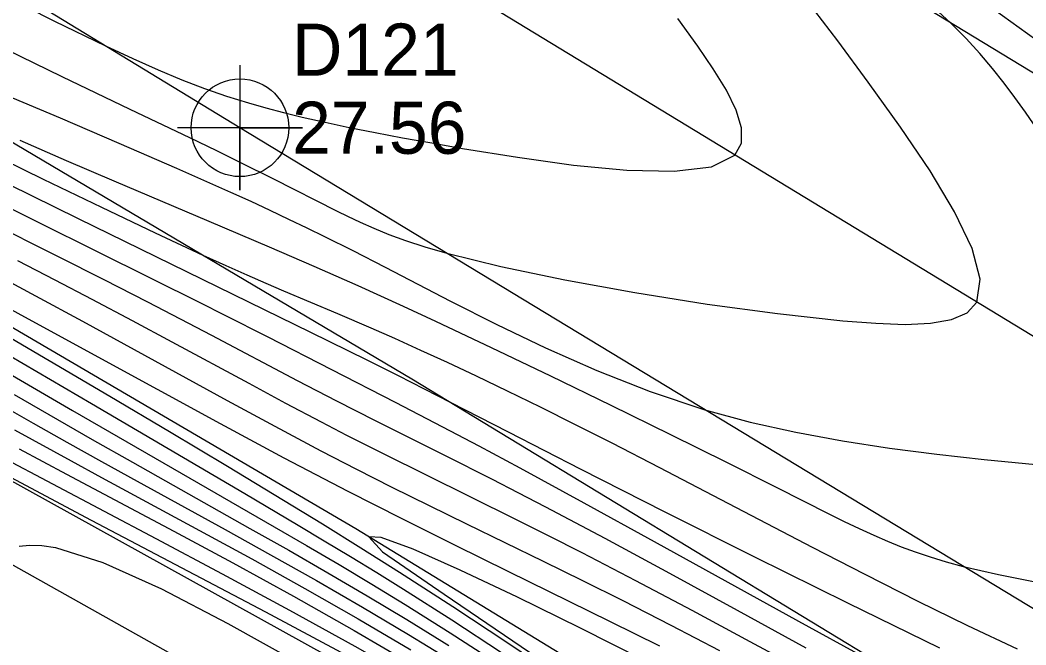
# Model space of a CAD drawing. Extents: x 2356077 to 2359823, y 225951 to 227822.
# Drawn here: x 2356454.61 to 2356502.87, y 227359.99 to 227389.97 of the extents above; entities that cross this region are included whole.
import ezdxf

# ---------------------------------------------------------------- set-up
doc = ezdxf.new("R2010")
doc.units = 0
for name, color, linetype in [('DTM Contours Major', 7, 'Continuous'), ('DTM Contours Minor', 7, 'Continuous'), ('Exist DTM Breakline', 7, 'Continuous'), ('Exist DTM Crownline', 7, 'Continuous'), ('Exist Roads EOP', 7, 'Continuous'), ('Exist Roads EOP Cogo Elevation', 7, 'Continuous'), ('Exist Roads EOP Cogo Number', 7, 'Continuous'), ('Exist Roads EOP Cogo Point CELL', 7, 'Continuous'), ('PH Exist DTM Breakline', 7, 'Continuous')]:
    doc.layers.add(name, color=color, linetype=linetype)

msp = doc.modelspace()

# ---------------------------------------------------------------- linework, layer by layer
at = {"layer": 'DTM Contours Major'}
for points in [[(2356503.336, 227389.017), (2356501.338, 227390.466), (2356499.11, 227392.097), (2356494.152, 227395.755), (2356488.824, 227399.691), (2356478.635, 227407.192), (2356476.063, 227409.092), (2356473.475, 227411.013), (2356472.171, 227411.984), (2356462.737, 227419.043), (2356459.663, 227421.332), (2356456.7, 227423.52), (2356453.891, 227425.566)], [(2356454.591, 227384.202), (2356456.817, 227383.239), (2356459.111, 227382.259), (2356463.673, 227380.327), (2356466.567, 227379.093), (2356468.708, 227378.164), (2356470.809, 227377.231), (2356472.991, 227376.238), (2356474.536, 227375.522), (2356477.209, 227374.261), (2356480.054, 227372.898), (2356482.96, 227371.488), (2356485.814, 227370.088), (2356488.505, 227368.753), (2356490.922, 227367.539), (2356493.408, 227366.282), (2356494.153, 227365.915), (2356494.87, 227365.571), (2356495.57, 227365.25), (2356496.221, 227364.967), (2356496.879, 227364.7), (2356497.558, 227364.447), (2356498.272, 227364.206), (2356499.036, 227363.975), (2356499.865, 227363.751), (2356501.56, 227363.358), (2356503.473, 227362.982)], [(2356492.468, 227358.61), (2356489.639, 227360.142), (2356486.851, 227361.639), (2356484.151, 227363.069), (2356481.582, 227364.403), (2356479.957, 227365.229), (2356478.402, 227366.007), (2356474.073, 227368.142), (2356472.106, 227369.12), (2356470.295, 227370.041), (2356469.068, 227370.678), (2356467.363, 227371.579), (2356465.596, 227372.527), (2356461.908, 227374.518), (2356460.004, 227375.54), (2356458.071, 227376.566), (2356456.293, 227377.495), (2356454.498, 227378.421)], [(2356448.17, 227376.445), (2356457.12, 227371.24), (2356461.502, 227368.703), (2356466.804, 227365.654), (2356468.36, 227364.753), (2356469.919, 227363.838), (2356471.491, 227362.898), (2356473.086, 227361.925), (2356475.245, 227360.57), (2356477.454, 227359.143)], [(2356485.329, 227350.492), (2356479.719, 227354.504), (2356478.749, 227355.126), (2356477.772, 227355.742), (2356476.779, 227356.357), (2356475.758, 227356.977), (2356474.698, 227357.608), (2356473.588, 227358.257), (2356470.681, 227359.908), (2356467.549, 227361.635), (2356464.322, 227363.38), (2356461.133, 227365.083), (2356453.705, 227369.014)]]:
    msp.add_lwpolyline(points, dxfattribs=at)
at = {"layer": 'DTM Contours Minor'}
for points in [[(2356453.561, 227391.29), (2356456.269, 227389.926), (2356458.703, 227388.738), (2356460.022, 227388.123), (2356461.237, 227387.584), (2356462.374, 227387.111), (2356463.458, 227386.694), (2356464.516, 227386.325), (2356465.573, 227385.994), (2356466.401, 227385.758), (2356467.256, 227385.534), (2356468.152, 227385.316), (2356469.242, 227385.069), (2356470.405, 227384.823), (2356471.644, 227384.576), (2356472.961, 227384.326), (2356474.359, 227384.074), (2356475.841, 227383.817), (2356478.47, 227383.387), (2356481.159, 227383.013), (2356483.727, 227382.766), (2356485.995, 227382.716), (2356487.782, 227382.934), (2356488.91, 227383.493), (2356489.222, 227384.07), (2356489.223, 227384.798), (2356488.965, 227385.653), (2356488.497, 227386.608), (2356487.869, 227387.639), (2356487.132, 227388.721), (2356486.173, 227390.043)], [(2356503.414, 227384.742), (2356502.847, 227385.553), (2356502.343, 227386.252), (2356501.82, 227386.949), (2356501.263, 227387.65), (2356500.659, 227388.362), (2356499.993, 227389.091), (2356499.253, 227389.845), (2356497.546, 227391.42)], [(2356451.94, 227389.541), (2356456.617, 227387.266), (2356459.871, 227385.704), (2356462.747, 227384.33), (2356464.036, 227383.709), (2356465.223, 227383.129), (2356466.732, 227382.376), (2356469.83, 227380.8), (2356470.315, 227380.56), (2356470.928, 227380.269), (2356471.583, 227379.978), (2356472.302, 227379.686), (2356473.11, 227379.391), (2356474.028, 227379.092), (2356475.079, 227378.788), (2356477.677, 227378.147), (2356480.747, 227377.506), (2356484.104, 227376.895), (2356487.569, 227376.344), (2356490.957, 227375.883), (2356494.089, 227375.543), (2356495.667, 227375.42), (2356497.078, 227375.37), (2356498.297, 227375.421), (2356499.293, 227375.597), (2356500.042, 227375.926), (2356500.513, 227376.433), (2356500.679, 227377.537), (2356500.289, 227379.009), (2356499.449, 227380.769), (2356498.268, 227382.739), (2356496.852, 227384.838), (2356495.307, 227386.989), (2356493.838, 227388.971), (2356492.372, 227390.896)], [(2356453.748, 227386.447), (2356456.527, 227385.273), (2356459.356, 227384.066), (2356462.122, 227382.866), (2356464.712, 227381.714), (2356465.675, 227381.275), (2356466.6, 227380.846), (2356467.494, 227380.425), (2356468.365, 227380.007), (2356469.22, 227379.589), (2356470.577, 227378.911), (2356472.125, 227378.118), (2356475.263, 227376.488), (2356477.478, 227375.364), (2356479.822, 227374.237), (2356482.28, 227373.15), (2356484.835, 227372.146), (2356487.471, 227371.27), (2356489.635, 227370.682), (2356491.835, 227370.19), (2356494.065, 227369.78), (2356496.318, 227369.436), (2356498.589, 227369.144), (2356500.871, 227368.89), (2356503.343, 227368.651)], [(2356502.461, 227359.79), (2356500.079, 227360.905), (2356497.699, 227362.075), (2356495.161, 227363.358), (2356492.631, 227364.661), (2356485.306, 227368.484), (2356483.021, 227369.662), (2356481.262, 227370.553), (2356479.584, 227371.388), (2356477.995, 227372.165), (2356476.503, 227372.881), (2356475.116, 227373.535), (2356473.84, 227374.123), (2356472.591, 227374.686), (2356471.447, 227375.189), (2356469.85, 227375.872), (2356467.261, 227376.964), (2356466.416, 227377.327), (2356465.5, 227377.727), (2356464.499, 227378.173), (2356463.397, 227378.674), (2356461.111, 227379.739), (2356458.529, 227380.971), (2356455.74, 227382.324), (2356452.831, 227383.753)], [(2356492.328, 227359.827), (2356489.028, 227361.645), (2356485.779, 227363.419), (2356482.68, 227365.089), (2356479.83, 227366.598), (2356478.512, 227367.282), (2356477.272, 227367.918), (2356474.994, 227369.069), (2356471.667, 227370.739), (2356469.812, 227371.684), (2356467.921, 227372.666), (2356463.808, 227374.833), (2356462.311, 227375.616), (2356460.744, 227376.429), (2356458.647, 227377.502), (2356456.454, 227378.613), (2356449.566, 227382.07)], [(2356498.745, 227359.834), (2356494.329, 227361.983), (2356489.862, 227364.199), (2356485.534, 227366.375), (2356481.533, 227368.407), (2356478.047, 227370.19), (2356475.266, 227371.618), (2356472.766, 227372.898), (2356471.259, 227373.656), (2356468.562, 227374.984), (2356457.415, 227380.437), (2356454.066, 227382.084)], [(2356495.127, 227359.38), (2356491.969, 227361.113), (2356485.049, 227364.934), (2356481.67, 227366.793), (2356478.602, 227368.466), (2356476.634, 227369.522), (2356474.895, 227370.442), (2356472.625, 227371.623), (2356466.514, 227374.748), (2356464.425, 227375.809), (2356463.281, 227376.385), (2356460.933, 227377.558), (2356452.872, 227381.552)], [(2356444.906, 227379.243), (2356458.039, 227371.565), (2356465.393, 227367.247), (2356467.948, 227365.737), (2356469.203, 227364.988), (2356470.457, 227364.23), (2356471.721, 227363.456), (2356473.006, 227362.657), (2356475.321, 227361.183), (2356477.711, 227359.622)], [(2356488.189, 227359.699), (2356485.846, 227360.92), (2356483.54, 227362.098), (2356481.617, 227363.059), (2356479.729, 227363.986), (2356476.049, 227365.775), (2356474.248, 227366.656), (2356472.468, 227367.539), (2356470.775, 227368.397), (2356469.062, 227369.286), (2356466.847, 227370.464), (2356464.569, 227371.699), (2356457.627, 227375.504), (2356455.365, 227376.727), (2356453.973, 227377.469)], [(2356485.304, 227359.924), (2356482.938, 227361.1), (2356478.033, 227363.507), (2356475.508, 227364.751), (2356472.944, 227366.031), (2356470.347, 227367.355), (2356467.287, 227368.956), (2356464.227, 227370.595), (2356461.197, 227372.241), (2356455.364, 227375.432), (2356452.627, 227376.916)], [(2356453.08, 227375.348), (2356456.004, 227373.635), (2356458.914, 227371.921), (2356461.779, 227370.224), (2356464.568, 227368.557), (2356467.25, 227366.936), (2356469.12, 227365.791), (2356470.961, 227364.648), (2356472.817, 227363.475), (2356475.374, 227361.822), (2356478.004, 227360.087), (2356480.673, 227358.294)], [(2356452.196, 227372.362), (2356455.245, 227370.629), (2356456.852, 227369.724), (2356458.513, 227368.794), (2356460.229, 227367.841), (2356464.443, 227365.521), (2356466.622, 227364.312), (2356468.828, 227363.07), (2356471.043, 227361.794), (2356473.252, 227360.482), (2356475.133, 227359.327)], [(2356454.32, 227372.002), (2356458.074, 227369.85), (2356460, 227368.753), (2356461.948, 227367.653), (2356465.638, 227365.58), (2356467.5, 227364.527), (2356469.375, 227363.452), (2356471.261, 227362.347), (2356473.161, 227361.206), (2356475.182, 227359.952)], [(2356454.348, 227370.307), (2356457.059, 227368.815), (2356458.519, 227368.02), (2356463.223, 227365.476), (2356465.727, 227364.11), (2356468.279, 227362.694), (2356470.839, 227361.237), (2356473.365, 227359.748)], [(2356454.561, 227369.39), (2356456.835, 227368.176), (2356461.99, 227365.442), (2356464.821, 227363.92), (2356467.728, 227362.326), (2356470.638, 227360.683), (2356473.483, 227359.012)], [(2356484.517, 227350.402), (2356479.289, 227354.14), (2356477.483, 227355.105), (2356477.251, 227355.263), (2356476.912, 227355.582), (2356476.646, 227355.79), (2356476.295, 227356.037), (2356475.861, 227356.319), (2356473.499, 227357.714), (2356470.249, 227359.502), (2356466.397, 227361.556), (2356458.033, 227365.959), (2356453.685, 227368.276)], [(2356484.568, 227359.245), (2356481.495, 227360.792), (2356478.47, 227362.277), (2356475.719, 227363.579), (2356473.465, 227364.577), (2356471.933, 227365.149), (2356471.347, 227365.176), (2356471.994, 227364.459), (2356474.965, 227362.418), (2356487.283, 227354.045)], [(2356454.567, 227364.733), (2356455.07, 227364.78), (2356455.65, 227364.759), (2356456.316, 227364.656), (2356458.585, 227363.934), (2356461.396, 227362.67), (2356464.579, 227361.016), (2356467.963, 227359.124)]]:
    msp.add_lwpolyline(points, dxfattribs=at)
at = {"layer": 'Exist DTM Breakline'}
msp.add_lwpolyline([(2356395.613, 227396.758), (2356486.533, 227345.705)], dxfattribs=at)
at = {"layer": 'Exist DTM Crownline'}
msp.add_lwpolyline([(2357542.756, 226741.609), (2357459.889, 226792.427), (2357374.177, 226844.74), (2357291.426, 226895.083), (2357208.118, 226946.275), (2357125.882, 226996.539), (2357045.017, 227045.595), (2356966.337, 227093.498), (2356883.413, 227143.712), (2356799.704, 227194.618), (2356722.637, 227241.528), (2356636.765, 227293.74), (2356553.053, 227344.465), (2356470.397, 227394.758), (2356383.201, 227447.638), (2356299.889, 227498.478), (2356223.248, 227545.375)], dxfattribs=at)
at = {"layer": 'Exist Roads EOP'}
for points in [[(2357548.158, 226751.097), (2357465.654, 226801.744), (2357379.741, 226854.27), (2357296.317, 226905.048), (2357214.489, 226955.136), (2357131.706, 227005.719), (2357050.471, 227054.837), (2356971.347, 227103.361), (2356888.766, 227153.021), (2356805.008, 227204.071), (2356729.232, 227250.322), (2356641.873, 227303.321), (2356558.204, 227353.943), (2356475.441, 227404.348), (2356389.192, 227456.864), (2356305.906, 227507.596), (2356229.771, 227554.142)], [(2357548.158, 226751.097), (2357551.518, 226748.955), (2357539.932, 226730.044), (2357536.732, 226732.588), (2357457.094, 226780.918), (2357368.575, 226834.971), (2357285.95, 226885.112), (2357202.56, 226936.462), (2357119.743, 226986.718), (2357040.047, 227034.838), (2356959.55, 227083.993), (2356876.77, 227134.388), (2356794.33, 227184.148), (2356716.529, 227232.438), (2356632.17, 227283.448), (2356547.589, 227334.799), (2356465.16, 227384.805), (2356376.528, 227438.798), (2356293.908, 227488.913), (2356217.843, 227535.566)]]:
    msp.add_lwpolyline(points, dxfattribs=at)
at = {"layer": 'Exist Roads EOP Cogo Point CELL'}
msp.add_lwpolyline([(2356465.16, 227387.805), (2356465.16, 227381.805), (2356465.16, 227384.805), (2356468.16, 227384.805), (2356462.16, 227384.805)], dxfattribs=at)
msp.add_circle((2356465.16, 227384.805), 2.344, dxfattribs=at)
at = {"layer": 'PH Exist DTM Breakline'}
for points in [[(2356355.835, 227442.663), (2356385.919, 227425.194), (2356415.811, 227406.666), (2356443.878, 227390.232), (2356473.404, 227372.748), (2356501.523, 227355.674), (2356528.621, 227339.213), (2356543.022, 227329.128), (2356552.137, 227319.323), (2356555.467, 227312.405), (2356554.394, 227306.239), (2356549.197, 227297.848)], [(2356547.307, 227306.571), (2356542.97, 227311.331), (2356530.826, 227318.158), (2356509.361, 227333.838), (2356477.162, 227355.128), (2356446.028, 227372.373), (2356422.419, 227387.452), (2356398.28, 227401.994), (2356373.932, 227416.38), (2356353.156, 227428.562)], [(2356550.383, 227312.732), (2356539.292, 227320.934), (2356527.778, 227329.701), (2356512.485, 227339.892), (2356493.823, 227351.428), (2356470.72, 227365.56), (2356448.885, 227378.338), (2356429.689, 227389.183), (2356404.633, 227405.564)]]:
    msp.add_lwpolyline(points, dxfattribs=at)

# ---------------------------------------------------------------- texts
at = {"layer": 'Exist Roads EOP Cogo Elevation'}
msp.add_text('27.56', height=2.5, dxfattribs=at).set_placement((2356467.66, 227383.555))
at = {"layer": 'Exist Roads EOP Cogo Number'}
msp.add_text('D121', height=2.5, dxfattribs=at).set_placement((2356467.66, 227387.305))

doc.saveas('drawing.dxf')
